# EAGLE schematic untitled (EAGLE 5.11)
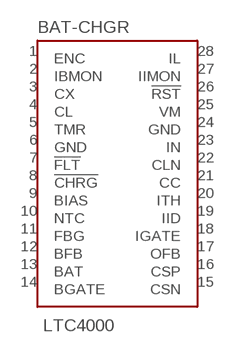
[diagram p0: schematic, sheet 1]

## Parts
BAT-CHGR  LTC4000  [SSOP-28]
Unconnected: BAT-CHGR.1(ENC) BAT-CHGR.2(IBMON) BAT-CHGR.3(CX) BAT-CHGR.4(CL) BAT-CHGR.5(TMR) BAT-CHGR.6(GND) BAT-CHGR.7(!FLT) BAT-CHGR.8(!CHRG) BAT-CHGR.9(BIAS) BAT-CHGR.10(NTC) BAT-CHGR.11(FBG) BAT-CHGR.12(BFB) BAT-CHGR.13(BAT) BAT-CHGR.14(BGATE) BAT-CHGR.15(CSN) BAT-CHGR.16(CSP) BAT-CHGR.17(OFB) BAT-CHGR.18(IGATE) BAT-CHGR.19(IID) BAT-CHGR.20(ITH) BAT-CHGR.21(CC) BAT-CHGR.22(CLN) BAT-CHGR.23(IN) BAT-CHGR.24(GND) BAT-CHGR.25(VM) BAT-CHGR.26(!RST) BAT-CHGR.27(IIMON) BAT-CHGR.28(IL)

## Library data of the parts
BAT-CHGR = trl:LTC4000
